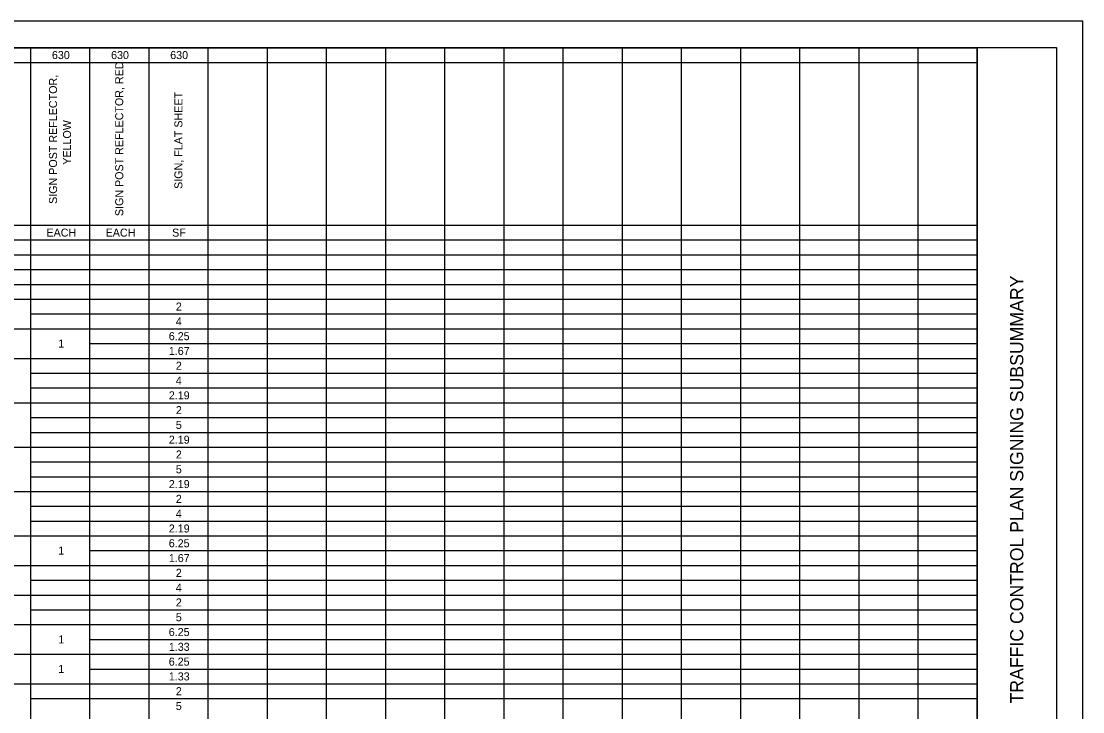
# Model space of a CAD drawing. Extents: x 0 to 34, y 0 to 22.
# Drawn here: x 13.91 to 34, y 8.93 to 22 of the extents above; entities that cross this region are included whole.
import ezdxf

# ---------------------------------------------------------------- set-up
doc = ezdxf.new("R2010")
doc.units = 0
for name, color, linetype in [('SH_Border', 7, 'Continuous'), ('SH_Cut_Line', 7, 'Continuous'), ('SH_Data', 7, 'Continuous'), ('SH_Text', 7, 'Continuous')]:
    doc.layers.add(name, color=color, linetype=linetype)

msp = doc.modelspace()

# ---------------------------------------------------------------- linework, layer by layer
at = {"layer": 'SH_Border'}
msp.add_line((32, 0.5), (32, 21.5), dxfattribs=at)
msp.add_lwpolyline([(1.5, 21.5), (33.5, 21.5), (33.5, 0.5), (1.5, 0.5)], close=True, dxfattribs=at)
at = {"layer": 'SH_Cut_Line'}
msp.add_lwpolyline([(0, 0), (34, 0), (34, 22), (0, 22)], close=True, dxfattribs=at)
at = {"layer": 'SH_Text'}
for p, q in [((1.5, 21.499), (32, 21.499)), ((14.082, 21.499), (14.082, 0.502)), ((15.202, 21.499), (15.202, 0.782)), ((16.322, 21.499), (16.322, 0.502)), ((17.442, 21.499), (17.442, 0.502)), ((18.562, 21.499), (18.562, 0.502)), ((19.681, 21.499), (19.681, 0.502)), ((20.801, 21.499), (20.801, 0.502)), ((21.921, 21.499), (21.921, 0.502)), ((23.041, 21.499), (23.041, 0.502)), ((24.161, 21.499), (24.161, 0.502)), ((25.281, 21.499), (25.281, 0.502)), ((26.401, 21.499), (26.401, 0.502)), ((27.521, 21.499), (27.521, 0.502)), ((28.64, 21.499), (28.64, 0.502)), ((29.76, 21.499), (29.76, 0.502)), ((30.88, 21.499), (30.88, 0.502)), ((32, 21.499), (32, 0.502)), ((10.722, 21.219), (32, 21.219)), ((10.722, 18.14), (32, 18.14)), ((1.5, 17.86), (32, 17.86)), ((1.5, 17.58), (32, 17.58)), ((1.5, 17.3), (32, 17.3)), ((1.5, 17.02), (32, 17.02)), ((1.5, 16.74), (32, 16.74)), ((14.082, 16.46), (32, 16.46)), ((1.5, 16.18), (32, 16.18)), ((15.202, 15.9), (32, 15.9)), ((1.5, 15.62), (32, 15.62)), ((14.082, 15.34), (32, 15.34)), ((14.082, 15.06), (32, 15.06)), ((1.5, 14.78), (32, 14.78)), ((14.082, 14.5), (32, 14.5)), ((14.082, 14.22), (32, 14.22)), ((1.5, 13.94), (32, 13.94)), ((14.082, 13.66), (32, 13.66)), ((14.082, 13.38), (32, 13.38)), ((1.5, 13.1), (32, 13.1)), ((14.082, 12.82), (32, 12.82)), ((14.082, 12.54), (32, 12.54)), ((1.5, 12.261), (32, 12.261)), ((15.202, 11.981), (32, 11.981)), ((1.5, 11.701), (32, 11.701)), ((14.082, 11.421), (32, 11.421)), ((1.5, 11.141), (32, 11.141)), ((14.082, 10.861), (32, 10.861)), ((1.5, 10.581), (32, 10.581)), ((15.202, 10.301), (32, 10.301)), ((1.5, 10.021), (32, 10.021)), ((15.202, 9.741), (32, 9.741)), ((1.5, 9.461), (32, 9.461)), ((14.082, 9.181), (32, 9.181))]:
    msp.add_line(p, q, dxfattribs=at)

# ---------------------------------------------------------------- texts
at = {"layer": 'SH_Data'}
msp.add_text('TRAFFIC CONTROL PLAN SIGNING SUBSUMMARY', height=0.25, rotation=90, dxfattribs=at).set_placement((32.875, 9.088))
at = {"layer": 'SH_Text'}
for s, height, p in [('630', 0.1515, (14.488, 21.284)), ('630', 0.1515, (15.608, 21.284)), ('630', 0.1515, (16.727, 21.284)), ('EACH', 0.1515, (14.385, 17.924)), ('EACH', 0.1515, (15.505, 17.924)), ('SF', 0.1515, (16.764, 17.924)), ('2', 0.152, (16.834, 16.524)), ('4', 0.152, (16.833, 16.244)), ('6.25', 0.1515, (16.7, 15.964)), ('1', 0.152, (14.607, 15.824)), ('1.67', 0.1515, (16.701, 15.684)), ('2', 0.152, (16.834, 15.404)), ('4', 0.152, (16.833, 15.124)), ('2.19', 0.1515, (16.701, 14.844)), ('2', 0.152, (16.834, 14.564)), ('5', 0.152, (16.833, 14.285)), ('2.19', 0.1515, (16.701, 14.005)), ('2', 0.152, (16.834, 13.725)), ('5', 0.152, (16.833, 13.445)), ('2.19', 0.1515, (16.701, 13.165)), ('2', 0.152, (16.834, 12.885)), ('4', 0.152, (16.833, 12.605)), ('2.19', 0.1515, (16.701, 12.325)), ('1', 0.152, (14.607, 11.905)), ('6.25', 0.1515, (16.7, 12.045)), ('1.67', 0.1515, (16.701, 11.765)), ('2', 0.152, (16.834, 11.485)), ('4', 0.152, (16.833, 11.205)), ('2', 0.152, (16.834, 10.925)), ('5', 0.152, (16.833, 10.645)), ('6.25', 0.1515, (16.7, 10.365)), ('1', 0.152, (14.607, 10.225)), ('1.33', 0.1515, (16.701, 10.085)), ('6.25', 0.1515, (16.7, 9.805)), ('1', 0.152, (14.607, 9.665)), ('1.33', 0.1515, (16.701, 9.525)), ('2', 0.152, (16.834, 9.245)), ('5', 0.152, (16.833, 8.965))]:
    msp.add_text(s, height=height, dxfattribs=at).set_placement(p)
for s, height, p in [('SIGN POST REFLECTOR, RED', 0.15151, (15.838, 18.312)), ('SIGN POST REFLECTOR, ', 0.15151, (14.585, 18.543)), ('SIGN, FLAT SHEET', 0.15151, (16.958, 18.827)), ('YELLOW', 0.1515, (14.85, 19.284))]:
    msp.add_text(s, height=height, rotation=90, dxfattribs=at).set_placement(p)

doc.saveas('drawing.dxf')
